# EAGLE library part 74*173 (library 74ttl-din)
4-bit D type REGISTER, 3-state
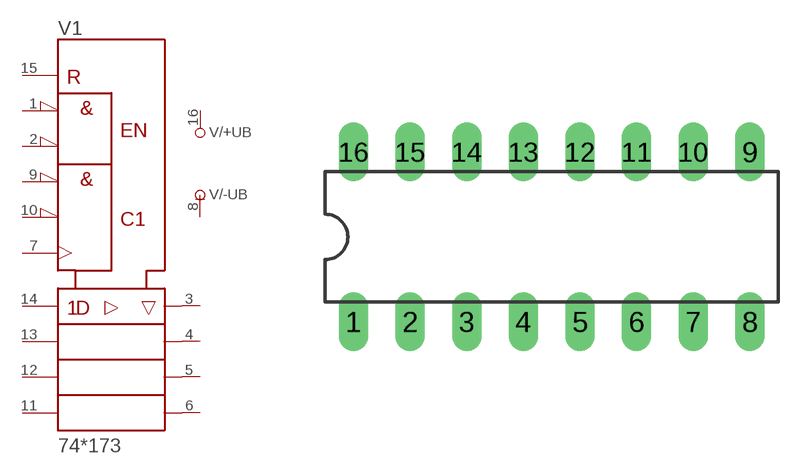
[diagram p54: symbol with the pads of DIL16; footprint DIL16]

Designator prefix V; gates /+UB=+UB /-UB=-UB 1=173

## 74173N  [DIL16]
1  1:M  in
2  1:N  in
3  1:1Q  hiz
4  1:2Q  hiz
5  1:3Q  hiz
6  1:4Q  hiz
7  1:CLK  in
8  /-UB:-UB  pwr
9  1:G\1  in
10  1:G\2  in
11  1:4D  in
12  1:3D  in
13  1:2D  in
14  1:1D  in
15  1:CLR  in
16  /+UB:+UB  pwr

## Footprint DIL16 (pad centres in mm)
Dual In Line Package
drill 0.813 long: 1 -8.89,-3.81; 2 -6.35,-3.81; 3 -3.81,-3.81; 4 -1.27,-3.81; 5 1.27,-3.81; 6 3.81,-3.81; 7 6.35,-3.81; 8 8.89,-3.81; 9 8.89,3.81; 10 6.35,3.81; 11 3.81,3.81; 12 1.27,3.81; 13 -1.27,3.81; 14 -3.81,3.81; 15 -6.35,3.81; 16 -8.89,3.81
